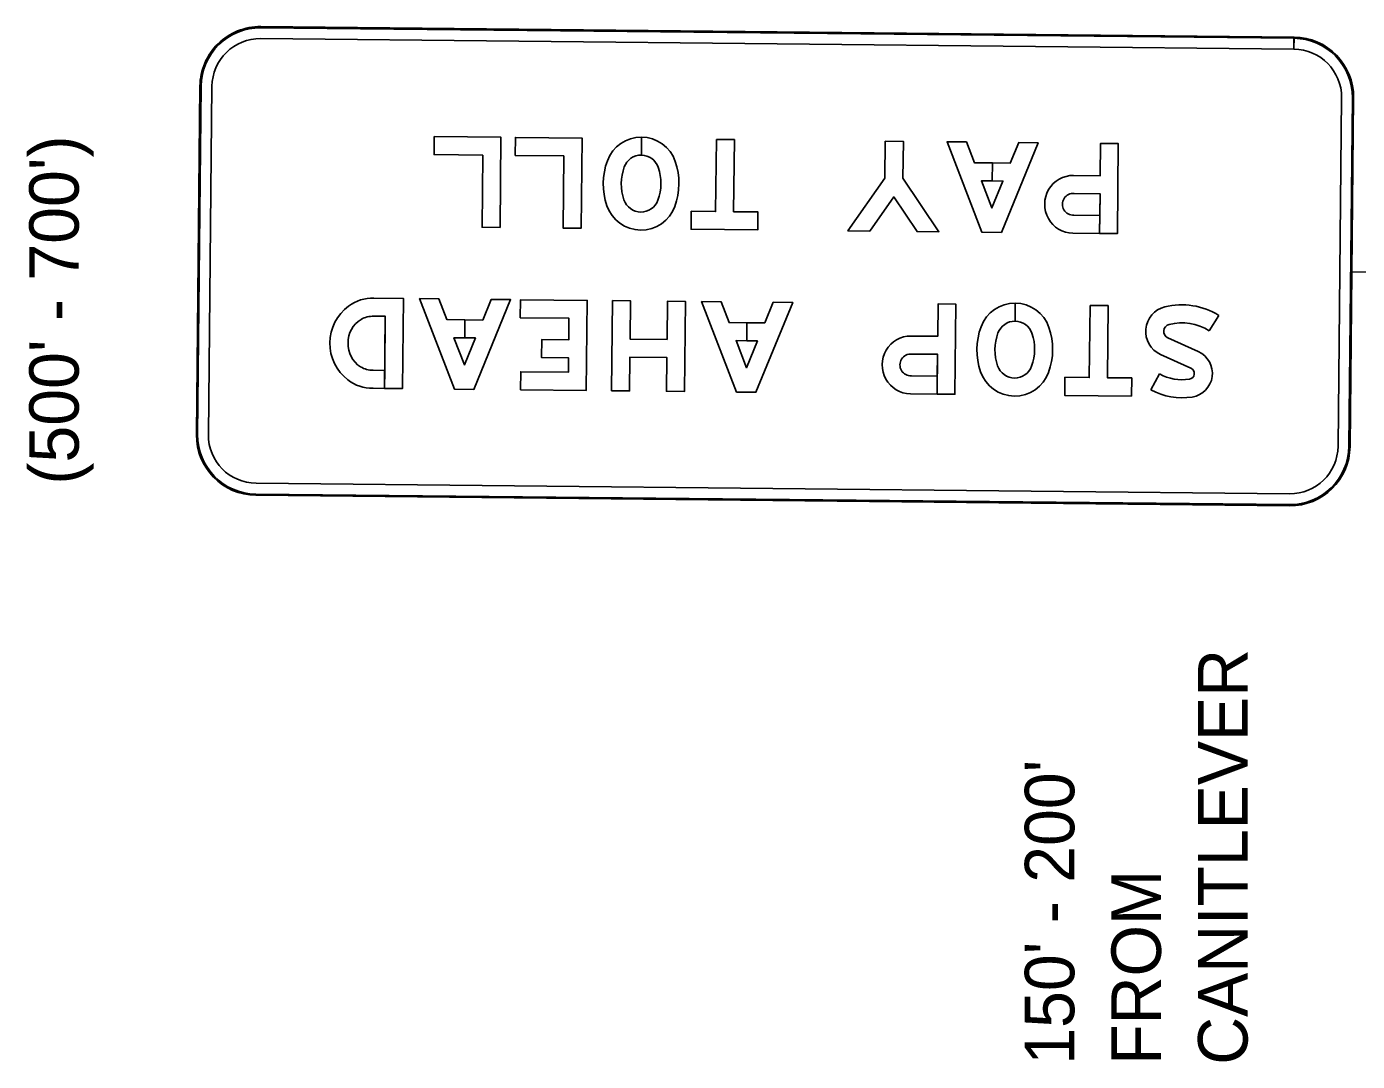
# Model space of a CAD drawing. Extents: x -102643 to -98250, y 54554 to 62384.
# Drawn here: x -102543 to -101620, y 57354 to 58072 of the extents above; entities that cross this region are included whole.
import ezdxf

# ---------------------------------------------------------------- set-up
doc = ezdxf.new("R2010")
doc.units = 0
for name, color, linetype in [('LeaderLine_dp', 7, 'Continuous'), ('SignPanel', 7, 'Continuous'), ('TextLabel', 7, 'Continuous')]:
    doc.layers.add(name, color=color, linetype=linetype)

msp = doc.modelspace()

# ---------------------------------------------------------------- linework, layer by layer
at = {"layer": 'LeaderLine_dp'}
msp.add_line((-101624.05, 57901.32), (-101212.67, 57905.28), dxfattribs=at)
at = {"layer": 'SignPanel'}
for p, q in [((-102380.75, 58070.71), (-101664.08, 58063.43)), ((-101664.14, 58064.26), (-102380.74, 58071.54)), ((-101664.07, 58064.26), (-102380.74, 58071.54)), ((-101664.06, 58064.26), (-102380.74, 58071.54)), ((-102380.82, 58063.21), (-101664.23, 58055.93)), ((-101664.23, 58055.93), (-101664.14, 58064.26)), ((-101664.06, 58064.26), (-101664.15, 58055.93)), ((-101664.08, 58063.43), (-101664.07, 58064.26)), ((-101664.06, 58064.26), (-101664.07, 58063.43)), ((-102422.83, 58030.3), (-102425.28, 57788.59)), ((-102422.83, 58030.3), (-102425.28, 57788.59)), ((-102422.83, 58030.3), (-102425.28, 57788.59)), ((-102424.45, 57788.59), (-102421.99, 58030.29)), ((-102416.95, 57788.51), (-102414.49, 58030.21)), ((-101631.15, 58022.26), (-101633.61, 57780.55)), ((-101623.65, 58022.18), (-101626.11, 57780.48)), ((-101625.27, 57780.47), (-101622.82, 58022.17)), ((-101625.27, 57780.47), (-101622.82, 58022.17)), ((-101625.27, 57780.47), (-101622.82, 58022.17)), ((-102116.59, 57994.92), (-102116.71, 57982.42)), ((-102116.71, 57982.42), (-102116.58, 57994.92)), ((-102116.59, 57994.92), (-102116.71, 57982.42)), ((-102116.71, 57982.42), (-102116.58, 57994.92)), ((-101798.54, 57968.15), (-101817.08, 57968.33)), ((-101798.66, 57955.65), (-101816.57, 57955.83)), ((-102302.19, 57883.21), (-102302.19, 57883.21)), ((-101857.43, 57879.78), (-101857.56, 57867.28)), ((-101857.43, 57879.78), (-101857.56, 57867.28)), ((-101857.55, 57867.28), (-101857.43, 57879.78)), ((-101857.55, 57867.28), (-101857.43, 57879.78)), ((-102302.32, 57870.71), (-102302.32, 57870.71)), ((-102302.32, 57870.71), (-102294.32, 57870.63)), ((-102302.32, 57870.71), (-102294.32, 57870.63)), ((-101722.86, 57860.65), (-101716.26, 57871.26)), ((-101722.86, 57860.65), (-101716.26, 57871.26)), ((-101722.86, 57860.65), (-101716.26, 57871.26)), ((-101911.24, 57856.79), (-101929.78, 57856.97)), ((-101730.49, 57846.14), (-101751.55, 57855.64)), ((-101730.49, 57846.14), (-101751.55, 57855.64)), ((-101730.49, 57846.14), (-101751.55, 57855.64)), ((-101911.36, 57844.29), (-101929.27, 57844.47)), ((-101756.69, 57844.24), (-101735.62, 57834.75)), ((-101756.69, 57844.24), (-101735.62, 57834.75)), ((-101756.69, 57844.24), (-101735.62, 57834.75)), ((-101757.33, 57830.65), (-101763.35, 57819.69)), ((-101757.33, 57830.65), (-101763.35, 57819.69)), ((-101757.33, 57830.65), (-101763.35, 57819.69)), ((-101667.28, 57747.56), (-102383.96, 57754.84)), ((-102384.04, 57746.51), (-101667.36, 57739.23)), ((-102384.04, 57746.51), (-101667.36, 57739.23)), ((-102384.04, 57746.51), (-101667.36, 57739.23)), ((-101667.35, 57740.06), (-102384.03, 57747.34))]:
    msp.add_line(p, q, dxfattribs=at)
for points in [[(-102226.72, 57982.45), (-102260.46, 57982.79), (-102260.34, 57995.29), (-102214.09, 57994.82), (-102214.72, 57932.32), (-102227.22, 57932.45)], [(-102226.72, 57982.45), (-102260.46, 57982.79), (-102260.34, 57995.29), (-102214.09, 57994.82), (-102214.72, 57932.32), (-102227.22, 57932.45)], [(-102226.72, 57982.45), (-102260.46, 57982.79), (-102260.34, 57995.29), (-102214.09, 57994.82), (-102214.72, 57932.32), (-102227.22, 57932.45)], [(-102170.47, 57981.87), (-102204.22, 57982.22), (-102204.09, 57994.72), (-102157.84, 57994.25), (-102158.48, 57931.75), (-102170.98, 57931.88)], [(-102170.47, 57981.87), (-102204.22, 57982.22), (-102204.09, 57994.72), (-102157.84, 57994.25), (-102158.48, 57931.75), (-102170.98, 57931.88)], [(-102170.47, 57981.87), (-102204.22, 57982.22), (-102204.09, 57994.72), (-102157.84, 57994.25), (-102158.48, 57931.75), (-102170.98, 57931.88)], [(-102064.72, 57993.3), (-102052.22, 57993.17), (-102052.73, 57943.18), (-102035.86, 57943.01), (-102035.98, 57930.51), (-102082.23, 57930.98), (-102082.1, 57943.47), (-102065.23, 57943.3)], [(-102064.72, 57993.3), (-102052.22, 57993.17), (-102052.73, 57943.18), (-102035.86, 57943.01), (-102035.98, 57930.51), (-102082.23, 57930.98), (-102082.1, 57943.47), (-102065.23, 57943.3)], [(-102064.72, 57993.3), (-102052.22, 57993.17), (-102052.73, 57943.18), (-102035.86, 57943.01), (-102035.98, 57930.51), (-102082.23, 57930.98), (-102082.1, 57943.47), (-102065.23, 57943.3)], [(-101947.54, 57992.11), (-101935.04, 57991.98), (-101935.3, 57966.36), (-101910.37, 57929.23), (-101925.53, 57929.38), (-101941.68, 57953.44), (-101958.33, 57929.72), (-101973.49, 57929.87), (-101947.8, 57966.49)], [(-101947.54, 57992.11), (-101935.04, 57991.98), (-101935.3, 57966.36), (-101910.37, 57929.23), (-101925.53, 57929.38), (-101941.68, 57953.44), (-101958.33, 57929.72), (-101973.49, 57929.87), (-101947.8, 57966.49)], [(-101947.54, 57992.11), (-101935.04, 57991.98), (-101935.3, 57966.36), (-101910.37, 57929.23), (-101925.53, 57929.38), (-101941.68, 57953.44), (-101958.33, 57929.72), (-101973.49, 57929.87), (-101947.8, 57966.49)], [(-101885.71, 57977.11), (-101860.92, 57976.85), (-101855.06, 57991.17), (-101841.61, 57991.03), (-101867.08, 57928.79), (-101880.53, 57928.93), (-101904.73, 57991.68), (-101891.28, 57991.54)], [(-101873.44, 57964.48), (-101873.32, 57976.98), (-101860.92, 57976.85), (-101855.06, 57991.17), (-101841.61, 57991.03), (-101867.08, 57928.79), (-101880.53, 57928.93), (-101904.73, 57991.68), (-101891.28, 57991.54), (-101885.71, 57977.11), (-101873.32, 57976.98), (-101873.45, 57964.48), (-101880.87, 57964.56), (-101873.63, 57945.78), (-101866.01, 57964.41)], [(-101873.44, 57964.48), (-101873.32, 57976.98), (-101860.92, 57976.85), (-101855.06, 57991.17), (-101841.61, 57991.03), (-101867.08, 57928.79), (-101880.53, 57928.93), (-101904.73, 57991.68), (-101891.28, 57991.54), (-101885.71, 57977.11), (-101873.32, 57976.98), (-101873.45, 57964.48), (-101880.87, 57964.56), (-101873.63, 57945.78), (-101866.01, 57964.41)], [(-101866.01, 57964.41), (-101880.87, 57964.56), (-101873.63, 57945.78)], [(-102251.52, 57868.32), (-102226.73, 57868.06), (-102220.87, 57882.38), (-102207.42, 57882.24), (-102232.89, 57820), (-102246.34, 57820.14), (-102270.54, 57882.89), (-102257.09, 57882.75)], [(-102239.25, 57855.69), (-102239.13, 57868.19), (-102226.73, 57868.06), (-102220.87, 57882.38), (-102207.42, 57882.24), (-102232.89, 57820), (-102246.34, 57820.14), (-102270.54, 57882.89), (-102257.09, 57882.75), (-102251.52, 57868.32), (-102239.13, 57868.19), (-102239.26, 57855.69), (-102246.68, 57855.77), (-102239.44, 57836.99), (-102231.82, 57855.62)], [(-102239.25, 57855.69), (-102239.13, 57868.19), (-102226.73, 57868.06), (-102220.87, 57882.38), (-102207.42, 57882.24), (-102232.89, 57820), (-102246.34, 57820.14), (-102270.54, 57882.89), (-102257.09, 57882.75), (-102251.52, 57868.32), (-102239.13, 57868.19), (-102239.26, 57855.69), (-102246.68, 57855.77), (-102239.44, 57836.99), (-102231.82, 57855.62)], [(-102200.55, 57819.67), (-102200.43, 57832.17), (-102167.3, 57831.83), (-102167.2, 57841.83), (-102185.95, 57842.02), (-102185.82, 57854.52), (-102167.08, 57854.33), (-102166.92, 57869.33), (-102200.67, 57869.68), (-102200.54, 57882.17), (-102154.3, 57881.7), (-102154.93, 57819.21)], [(-102200.55, 57819.67), (-102200.43, 57832.17), (-102167.3, 57831.83), (-102167.2, 57841.83), (-102185.95, 57842.02), (-102185.82, 57854.52), (-102167.08, 57854.33), (-102166.92, 57869.33), (-102200.67, 57869.68), (-102200.54, 57882.17), (-102154.3, 57881.7), (-102154.93, 57819.21)], [(-102200.55, 57819.67), (-102200.43, 57832.17), (-102167.3, 57831.83), (-102167.2, 57841.83), (-102185.95, 57842.02), (-102185.82, 57854.52), (-102167.08, 57854.33), (-102166.92, 57869.33), (-102200.67, 57869.68), (-102200.54, 57882.17), (-102154.3, 57881.7), (-102154.93, 57819.21)], [(-102136.8, 57881.53), (-102124.3, 57881.4), (-102124.57, 57854.89), (-102098.94, 57854.63), (-102098.68, 57881.14), (-102086.18, 57881.01), (-102086.81, 57818.52), (-102099.31, 57818.64), (-102099.07, 57842.13), (-102124.7, 57842.39), (-102124.93, 57818.9), (-102137.43, 57819.03)], [(-102136.8, 57881.53), (-102124.3, 57881.4), (-102124.57, 57854.89), (-102098.94, 57854.63), (-102098.68, 57881.14), (-102086.18, 57881.01), (-102086.81, 57818.52), (-102099.31, 57818.64), (-102099.07, 57842.13), (-102124.7, 57842.39), (-102124.93, 57818.9), (-102137.43, 57819.03)], [(-102136.8, 57881.53), (-102124.3, 57881.4), (-102124.57, 57854.89), (-102098.94, 57854.63), (-102098.68, 57881.14), (-102086.18, 57881.01), (-102086.81, 57818.52), (-102099.31, 57818.64), (-102099.07, 57842.13), (-102124.7, 57842.39), (-102124.93, 57818.9), (-102137.43, 57819.03)], [(-102055.91, 57866.33), (-102031.11, 57866.08), (-102025.26, 57880.39), (-102011.8, 57880.26), (-102037.28, 57818.01), (-102050.73, 57818.15), (-102074.93, 57880.9), (-102061.48, 57880.76)], [(-102043.64, 57853.7), (-102043.51, 57866.2), (-102031.11, 57866.08), (-102025.26, 57880.39), (-102011.8, 57880.26), (-102037.28, 57818.01), (-102050.73, 57818.15), (-102074.93, 57880.9), (-102061.48, 57880.76), (-102055.91, 57866.33), (-102043.51, 57866.2), (-102043.64, 57853.7), (-102051.07, 57853.78), (-102043.83, 57835), (-102036.21, 57853.63)], [(-102043.64, 57853.7), (-102043.51, 57866.2), (-102031.11, 57866.08), (-102025.26, 57880.39), (-102011.8, 57880.26), (-102037.28, 57818.01), (-102050.73, 57818.15), (-102074.93, 57880.9), (-102061.48, 57880.76), (-102055.91, 57866.33), (-102043.51, 57866.2), (-102043.64, 57853.7), (-102051.07, 57853.78), (-102043.83, 57835), (-102036.21, 57853.63)], [(-101805.57, 57878.16), (-101793.07, 57878.04), (-101793.57, 57828.04), (-101776.7, 57827.87), (-101776.83, 57815.37), (-101823.07, 57815.84), (-101822.95, 57828.34), (-101806.07, 57828.17)], [(-101805.57, 57878.16), (-101793.07, 57878.04), (-101793.57, 57828.04), (-101776.7, 57827.87), (-101776.83, 57815.37), (-101823.07, 57815.84), (-101822.95, 57828.34), (-101806.07, 57828.17)], [(-101805.57, 57878.16), (-101793.07, 57878.04), (-101793.57, 57828.04), (-101776.7, 57827.87), (-101776.83, 57815.37), (-101823.07, 57815.84), (-101822.95, 57828.34), (-101806.07, 57828.17)], [(-102231.82, 57855.62), (-102246.68, 57855.77), (-102239.44, 57836.99)], [(-102036.21, 57853.63), (-102051.07, 57853.78), (-102043.83, 57835)]]:
    msp.add_lwpolyline(points, close=True, dxfattribs=at)
for points in [[(-101817.49, 57928.29), (-101786.62, 57927.97), (-101785.99, 57990.47), (-101798.31, 57990.59), (-101798.54, 57968.15)], [(-101786.62, 57927.97), (-101785.99, 57990.47), (-101798.31, 57990.59), (-101798.54, 57968.15), (-101817.08, 57968.33)], [(-101786.62, 57927.97), (-101785.99, 57990.47), (-101798.31, 57990.59), (-101798.54, 57968.15), (-101817.08, 57968.33)], [(-101816.72, 57940.78), (-101798.82, 57940.6), (-101798.66, 57955.65)], [(-101816.57, 57955.83), (-101798.66, 57955.65), (-101798.94, 57928.1), (-101786.62, 57927.97)], [(-101816.57, 57955.83), (-101798.66, 57955.65), (-101798.94, 57928.1), (-101786.62, 57927.97)], [(-101817.49, 57928.29), (-101798.95, 57928.1), (-101798.82, 57940.6), (-101816.72, 57940.78)], [(-101817.49, 57928.29), (-101798.95, 57928.1), (-101798.82, 57940.6), (-101816.72, 57940.78)], [(-102302.82, 57820.71), (-102282.43, 57820.5), (-102281.79, 57883), (-102302.19, 57883.21)], [(-102294.32, 57870.63), (-102294.82, 57820.63), (-102282.43, 57820.5), (-102281.79, 57883), (-102302.19, 57883.21)], [(-102294.32, 57870.63), (-102294.82, 57820.63), (-102282.43, 57820.5), (-102281.79, 57883), (-102302.19, 57883.21)], [(-101930.19, 57816.93), (-101899.32, 57816.61), (-101898.69, 57879.11), (-101911.01, 57879.23), (-101911.24, 57856.79)], [(-101899.32, 57816.61), (-101898.69, 57879.11), (-101911.01, 57879.23), (-101911.24, 57856.79), (-101929.78, 57856.97)], [(-101899.32, 57816.61), (-101898.69, 57879.11), (-101911.01, 57879.23), (-101911.24, 57856.79), (-101929.78, 57856.97)], [(-102302.7, 57833.21), (-102294.7, 57833.13), (-102294.32, 57870.63), (-102302.32, 57870.71)], [(-101929.42, 57829.42), (-101911.52, 57829.24), (-101911.36, 57844.29)], [(-101929.27, 57844.47), (-101911.36, 57844.29), (-101911.64, 57816.74), (-101899.32, 57816.61)], [(-101929.27, 57844.47), (-101911.36, 57844.29), (-101911.64, 57816.74), (-101899.32, 57816.61)], [(-102302.82, 57820.71), (-102294.83, 57820.63), (-102294.7, 57833.13), (-102302.7, 57833.21)], [(-102302.82, 57820.71), (-102294.83, 57820.63), (-102294.7, 57833.13), (-102302.7, 57833.21)], [(-101930.19, 57816.93), (-101911.65, 57816.74), (-101911.52, 57829.24), (-101929.42, 57829.42)], [(-101930.19, 57816.93), (-101911.65, 57816.74), (-101911.52, 57829.24), (-101929.42, 57829.42)]]:
    msp.add_lwpolyline(points, dxfattribs=at)
for centre, radius, start, end in [((-102381.16, 58029.87), 41.67, 89.41805, 179.41805), ((-102381.16, 58029.87), 41.67, 89.41805, 179.41805), ((-102381.16, 58029.87), 41.67, 89.41805, 179.41805), ((-102381.16, 58029.87), 40.83, 89.41805, 179.41805), ((-102381.16, 58029.87), 33.33, 89.41805, 179.41805), ((-101664.48, 58022.6), 40.83, 359.41805, 89.41805), ((-101664.48, 58022.6), 41.67, 359.41805, 89.41805), ((-101664.48, 58022.6), 41.67, 359.41805, 89.41805), ((-101664.48, 58022.6), 41.67, 359.41805, 89.41805), ((-101664.48, 58022.6), 33.33, 359.41805, 89.41805), ((-101857.68, 57854.78), 25, 19.0243, 159.8118), ((-101857.68, 57854.78), 25, 89.42521, 159.81179), ((-101857.68, 57854.78), 25, 89.42521, 159.81179), ((-101857.68, 57854.78), 25, 19.0243, 89.41805), ((-101857.68, 57854.78), 25, 19.0243, 89.41805), ((-101749.5, 57860.19), 17.5, 103.89556, 245.74234), ((-101749.5, 57860.19), 17.5, 103.89556, 245.74234), ((-101749.5, 57860.19), 17.5, 103.89556, 245.74234), ((-101741.99, 57829.86), 48.75, 58.13738, 103.89556), ((-101741.99, 57829.86), 48.75, 58.13738, 103.89556), ((-101741.99, 57829.86), 48.75, 58.13738, 103.89556), ((-101857.68, 57854.78), 12.5, 19.0243, 159.8118), ((-101857.68, 57854.78), 12.5, 89.43237, 159.8118), ((-101857.68, 57854.78), 12.5, 89.43237, 159.8118), ((-101857.68, 57854.78), 12.5, 19.0243, 89.41805), ((-101857.68, 57854.78), 12.5, 19.0243, 89.41805), ((-101749.5, 57860.19), 5, 103.89556, 245.74234), ((-101749.5, 57860.19), 5, 103.89556, 245.74234), ((-101749.5, 57860.19), 5, 103.89556, 245.74234), ((-101741.99, 57829.86), 36.25, 58.13738, 103.89556), ((-101741.99, 57829.86), 36.25, 58.13738, 103.89556), ((-101741.99, 57829.86), 36.25, 58.13738, 103.89556), ((-101837.45, 57847.34), 46.56, 159.81179, 199.0243), ((-101837.45, 57847.34), 46.56, 159.8118, 199.0243), ((-101837.45, 57847.34), 46.56, 159.8118, 199.0243), ((-101837.45, 57847.34), 34.06, 159.81179, 199.0243), ((-101837.45, 57847.34), 34.06, 159.81179, 199.0243), ((-101837.45, 57847.34), 34.06, 159.81179, 199.0243), ((-101878.06, 57847.76), 34.06, 339.81179, 19.0243), ((-101878.06, 57847.76), 34.06, 339.81179, 19.0243), ((-101878.06, 57847.76), 34.06, 339.81179, 19.0243), ((-101878.06, 57847.76), 46.56, 339.81179, 19.0243), ((-101878.06, 57847.76), 46.56, 339.8118, 19.0243), ((-101878.06, 57847.76), 46.56, 339.8118, 19.0243), ((-101737.29, 57831.04), 16.56, 278.9057, 65.74234), ((-101737.29, 57831.04), 16.56, 278.9057, 65.74234), ((-101737.29, 57831.04), 16.56, 278.9057, 65.74234), ((-101857.83, 57840.32), 25, 199.0243, 339.8118), ((-101857.83, 57840.32), 25, 199.0243, 339.81179), ((-101857.83, 57840.32), 25, 199.0243, 339.81179), ((-101857.83, 57840.32), 12.5, 199.0243, 339.8118), ((-101857.83, 57840.32), 12.5, 199.0243, 339.8118), ((-101857.83, 57840.32), 12.5, 199.0243, 339.8118), ((-101741.69, 57859.14), 32.5, 241.2394, 278.9057), ((-101741.69, 57859.14), 32.5, 241.2394, 278.9057), ((-101741.69, 57859.14), 32.5, 241.2394, 278.9057), ((-101737.29, 57831.04), 4.06, 278.9057, 65.74234), ((-101737.29, 57831.04), 4.06, 278.9057, 65.74234), ((-101737.29, 57831.04), 4.06, 278.9057, 65.74234), ((-101741.69, 57859.14), 45, 241.2394, 278.90571), ((-101741.69, 57859.14), 45, 241.2394, 278.90571), ((-101741.69, 57859.14), 45, 241.2394, 278.90571), ((-102383.62, 57788.17), 41.67, 179.41805, 269.41805), ((-102383.62, 57788.17), 41.67, 179.41805, 269.41805), ((-102383.62, 57788.17), 41.67, 179.41805, 269.41805), ((-102383.62, 57788.17), 40.83, 179.41805, 269.41805), ((-102383.62, 57788.17), 33.33, 179.41805, 269.41805), ((-101666.94, 57780.89), 41.67, 269.41805, 359.41805), ((-101666.94, 57780.89), 41.67, 269.41805, 359.41805), ((-101666.94, 57780.89), 41.67, 269.41805, 359.41805), ((-101666.94, 57780.89), 40.83, 269.41805, 359.41805), ((-101666.94, 57780.89), 33.33, 269.41805, 359.41805)]:
    msp.add_arc(centre, radius, start, end, dxfattribs=at)
for centre, major_axis, ratio, start_param, end_param in [((-102116.84, 57969.92), (-0.25, -25), 0.999997, 1.91299, 4.370195), ((-102116.84, 57969.92), (-0.25, -25), 0.999997, 3.141718, 4.370195), ((-102116.84, 57969.92), (-0.25, -25), 0.999997, 3.141718, 4.370195), ((-102116.84, 57969.92), (-0.25, -25), 0.999997, 1.91299, 3.141593), ((-102116.84, 57969.92), (-0.25, -25), 0.999997, 1.91299, 3.141593), ((-102096.6, 57962.48), (-0.47, -46.56), 0.999997, 4.370195, 5.054583), ((-102096.6, 57962.48), (-0.47, -46.56), 0.999997, 4.370195, 5.054583), ((-102096.6, 57962.48), (-0.47, -46.56), 0.999997, 4.370195, 5.054583), ((-102116.84, 57969.92), (-0.13, -12.5), 0.999997, 1.91299, 4.370195), ((-102116.84, 57969.92), (-0.13, -12.5), 0.999997, 3.141843, 4.370195), ((-102116.84, 57969.92), (-0.13, -12.5), 0.999997, 3.141843, 4.370195), ((-102116.84, 57969.92), (-0.13, -12.5), 0.999997, 1.91299, 3.141593), ((-102116.84, 57969.92), (-0.13, -12.5), 0.999997, 1.91299, 3.141593), ((-102137.22, 57962.89), (-0.47, -46.56), 0.999997, 1.228603, 1.91299), ((-102137.22, 57962.89), (-0.47, -46.56), 0.999997, 1.228603, 1.91299), ((-102137.22, 57962.89), (-0.47, -46.56), 0.999997, 1.228603, 1.91299), ((-102096.6, 57962.48), (-0.35, -34.06), 0.999997, 4.370195, 5.054583), ((-102096.6, 57962.48), (-0.35, -34.06), 0.999997, 4.370195, 5.054583), ((-102096.6, 57962.48), (-0.35, -34.06), 0.999997, 4.370195, 5.054583), ((-102137.22, 57962.89), (-0.35, -34.06), 0.999997, 1.228603, 1.91299), ((-102137.22, 57962.89), (-0.35, -34.06), 0.999997, 1.228603, 1.91299), ((-102137.22, 57962.89), (-0.35, -34.06), 0.999997, 1.228603, 1.91299), ((-101817.3, 57948.31), (-0.2, -20.02), 0.985881, 3.140988, 6.28379), ((-101817.3, 57948.31), (-0.2, -20.02), 0.985881, 3.140988, 6.28379), ((-101817.3, 57948.31), (-0.2, -20.02), 0.985881, 3.140988, 6.28379), ((-102116.98, 57955.45), (-0.25, -25), 0.999997, 5.054583, 7.511788), ((-102116.98, 57955.45), (-0.25, -25), 0.999997, 5.054583, 7.511788), ((-102116.98, 57955.45), (-0.25, -25), 0.999997, 5.054583, 7.511788), ((-102116.98, 57955.45), (-0.13, -12.5), 0.999997, 5.054583, 7.511788), ((-102116.98, 57955.45), (-0.13, -12.5), 0.999997, 5.054583, 7.511788), ((-102116.98, 57955.45), (-0.13, -12.5), 0.999997, 5.054583, 7.511788), ((-101817.28, 57948.31), (-0.08, -7.55), 0.985881, 3.056611, 6.368167), ((-101817.28, 57948.31), (-0.08, -7.55), 0.985881, 3.056611, 6.368167), ((-101817.28, 57948.31), (-0.08, -7.55), 0.985881, 3.056611, 6.368167), ((-102303.29, 57855.87), (-0.28, -27.35), 0.992006, 3.111301, 3.802985), ((-102303.29, 57855.87), (-0.28, -27.35), 0.992006, 3.111301, 3.802985), ((-102303.29, 57855.87), (-0.28, -27.35), 0.992006, 3.111301, 3.802985), ((-102301.86, 57852.26), (-0.32, -31.12), 0.992006, 3.769463, 4.722379), ((-102301.86, 57852.26), (-0.32, -31.12), 0.992006, 3.769463, 4.722379), ((-102301.86, 57852.26), (-0.32, -31.12), 0.992006, 3.769463, 4.722379), ((-102301.65, 57852.44), (-0.19, -18.67), 0.992006, 3.689617, 4.738495), ((-102301.65, 57852.44), (-0.19, -18.67), 0.992006, 3.689617, 4.738495), ((-102301.65, 57852.44), (-0.19, -18.67), 0.992006, 3.689617, 4.738495), ((-102302.79, 57853.8), (-0.17, -16.91), 0.992006, 3.123742, 3.672538), ((-102302.79, 57853.8), (-0.17, -16.91), 0.992006, 3.123742, 3.672538), ((-102302.79, 57853.8), (-0.17, -16.91), 0.992006, 3.123742, 3.672538), ((-101930, 57836.95), (-0.2, -20.02), 0.985875, 3.140988, 6.28379), ((-101930, 57836.95), (-0.2, -20.02), 0.985875, 3.140988, 6.28379), ((-101930, 57836.95), (-0.2, -20.02), 0.985875, 3.140988, 6.28379), ((-102301.87, 57851.64), (-0.32, -31.12), 0.992006, 4.702399, 5.655315), ((-102301.87, 57851.64), (-0.32, -31.12), 0.992006, 4.702399, 5.655315), ((-102301.87, 57851.64), (-0.32, -31.12), 0.992006, 4.702399, 5.655315), ((-102301.66, 57851.46), (-0.19, -18.67), 0.992006, 4.686283, 5.735161), ((-102301.66, 57851.46), (-0.19, -18.67), 0.992006, 4.686283, 5.735161), ((-102301.66, 57851.46), (-0.19, -18.67), 0.992006, 4.686283, 5.735161), ((-101929.97, 57836.95), (-0.08, -7.55), 0.985875, 3.056611, 6.368167), ((-101929.97, 57836.95), (-0.08, -7.55), 0.985875, 3.056611, 6.368167), ((-101929.97, 57836.95), (-0.08, -7.55), 0.985875, 3.056611, 6.368167), ((-102302.82, 57850.12), (-0.17, -16.91), 0.992006, 5.75224, 6.301036), ((-102302.82, 57850.12), (-0.17, -16.91), 0.992006, 5.75224, 6.301036), ((-102302.82, 57850.12), (-0.17, -16.91), 0.992006, 5.75224, 6.301036), ((-102303.37, 57848.06), (-0.28, -27.35), 0.992006, 5.621793, 6.313477), ((-102303.37, 57848.06), (-0.28, -27.35), 0.992006, 5.621793, 6.313477), ((-102303.37, 57848.06), (-0.28, -27.35), 0.992006, 5.621793, 6.313477)]:
    msp.add_ellipse(centre, major_axis=major_axis, ratio=ratio, start_param=start_param, end_param=end_param, dxfattribs=at)

# ---------------------------------------------------------------- texts
at = {"layer": 'TextLabel'}
for s, p in [("(500' - 700')", (-102506.89, 57753.93)), ('CANITLEVER', (-101696.32, 57351.62)), ("150' - 200' ", (-101816.49, 57351.62)), ('FROM', (-101756.41, 57351.62))]:
    msp.add_text(s, height=34.335, rotation=90, dxfattribs=at).set_placement(p)

doc.saveas('drawing.dxf')
